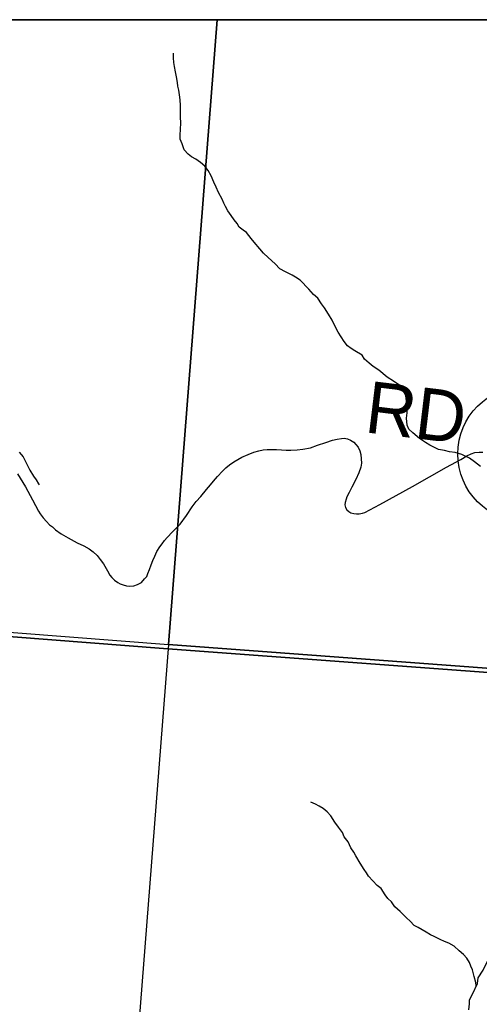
# Model space of a CAD drawing. Extents: x 0 to 82.7, y -0.2 to 22.
# Drawn here: x 7.785 to 8.291, y 19.817 to 20.9 of the extents above; entities that cross this region are included whole.
import ezdxf

# ---------------------------------------------------------------- set-up
doc = ezdxf.new("R2010")
doc.units = 0
for name, color, linetype in [('GM_X_County_Road', 7, 'Continuous'), ('GM_X_County_Road_Text', 7, 'Continuous'), ('GM_X_Minor_River', 7, 'Continuous'), ('GM_X_Section', 7, 'Continuous'), ('GM_X_Township_Text', 7, 'Continuous'), ('GM_X_Unincorporated', 7, 'Continuous'), ('SH_Cut_Line', 7, 'Continuous'), ('SH_Data', 7, 'Continuous')]:
    doc.layers.add(name, color=color, linetype=linetype)

msp = doc.modelspace()

# ---------------------------------------------------------------- linework, layer by layer
at = {"layer": 'GM_X_County_Road'}
for points in [[(8.0024, 20.9), (6.9771, 20.9), (6.9306, 20.2917), (7.9492, 20.2127)], [(8.9, 20.1421), (8.9, 20.9), (8.0024, 20.9), (7.9492, 20.2127)], [(8.9, 19.3224), (8.9, 20.1421), (7.9492, 20.2127), (7.8698, 19.2002), (8.8838, 19.1258)]]:
    msp.add_lwpolyline(points, close=True, dxfattribs=at)
msp.add_lwpolyline([(7.7829, 20.4005), (7.7918, 20.3861), (7.7995, 20.3718), (7.8062, 20.3594), (7.808, 20.3565), (7.8112, 20.3523), (7.8149, 20.3481), (7.8183, 20.3446), (7.8214, 20.3421), (7.8249, 20.3391), (7.831, 20.3346), (7.8387, 20.3302), (7.8484, 20.3247), (7.8558, 20.3212), (7.8618, 20.318), (7.866, 20.3149), (7.8706, 20.3107), (7.874, 20.3065), (7.8776, 20.3014), (7.8818, 20.2939), (7.8844, 20.2892), (7.8866, 20.2866), (7.8898, 20.2836), (7.8933, 20.2812), (7.8959, 20.2797), (7.8992, 20.2784), (7.9028, 20.2774), (7.9064, 20.2771), (7.9109, 20.2775), (7.9148, 20.2787), (7.9192, 20.2812), (7.9227, 20.2849), (7.9251, 20.2878), (7.9262, 20.2908), (7.928, 20.2952), (7.9301, 20.3004), (7.9319, 20.3051), (7.9339, 20.31), (7.9362, 20.3152), (7.9395, 20.3202), (7.9422, 20.3237), (7.9447, 20.3271), (7.9477, 20.3304), (7.9534, 20.3366), (7.9617, 20.3453), (7.969, 20.3547), (7.9752, 20.3644), (7.9795, 20.3701), (7.9845, 20.3757), (7.9908, 20.3832), (7.9954, 20.3885), (7.9985, 20.3924), (8.0029, 20.3978), (8.0083, 20.4033), (8.012, 20.4072), (8.0162, 20.4104), (8.021, 20.4139), (8.0298, 20.4189), (8.0365, 20.4217), (8.0429, 20.4244), (8.0485, 20.4259), (8.0531, 20.4268), (8.0574, 20.4273), (8.0635, 20.4273), (8.068, 20.4274), (8.0732, 20.427), (8.0785, 20.4267), (8.0837, 20.4266), (8.0904, 20.4269), (8.0969, 20.4277), (8.1053, 20.4293), (8.1131, 20.432), (8.1222, 20.4349), (8.1296, 20.4377), (8.1345, 20.4387), (8.1395, 20.4395), (8.1422, 20.4398), (8.1458, 20.439), (8.1493, 20.4374), (8.1529, 20.4352), (8.1552, 20.4329), (8.1576, 20.4299), (8.1595, 20.426), (8.1606, 20.4217), (8.1611, 20.417), (8.1612, 20.4123), (8.1607, 20.408), (8.1585, 20.4016), (8.1552, 20.3944), (8.1506, 20.3858), (8.1477, 20.3801), (8.1452, 20.3754), (8.1443, 20.3727), (8.1433, 20.3692), (8.1431, 20.3665), (8.1439, 20.3636), (8.1453, 20.361), (8.1474, 20.359), (8.1496, 20.3577), (8.1529, 20.3568), (8.1558, 20.3564), (8.1589, 20.3566), (8.1623, 20.3574), (8.1651, 20.3582), (8.1704, 20.3608), (8.1815, 20.3667), (8.2175, 20.3868), (8.2549, 20.4079), (8.2704, 20.4164), (8.2772, 20.4203), (8.282, 20.4225), (8.2859, 20.4239), (8.2907, 20.4244), (8.2947, 20.4244)], dxfattribs=at)
at = {"layer": 'GM_X_Minor_River'}
for points in [[(8.2921, 20.4085), (8.2857, 20.4139), (8.2801, 20.4178), (8.2718, 20.4217), (8.2642, 20.4241), (8.2581, 20.4249), (8.2525, 20.4261), (8.246, 20.4273), (8.2408, 20.4297), (8.2366, 20.432), (8.2317, 20.4351), (8.2253, 20.4394), (8.2178, 20.4456), (8.2133, 20.4498), (8.2114, 20.454), (8.2108, 20.4616), (8.2116, 20.4677), (8.2116, 20.4723), (8.2103, 20.4841), (8.2096, 20.4879), (8.2062, 20.494), (8.2036, 20.4978), (8.1964, 20.5025), (8.1897, 20.5067), (8.1803, 20.5145), (8.1742, 20.5187), (8.1697, 20.5222), (8.1645, 20.5268), (8.1619, 20.531), (8.154, 20.5357), (8.1498, 20.5384), (8.1461, 20.5415), (8.1423, 20.5461), (8.139, 20.5511), (8.1356, 20.5565), (8.1319, 20.5633), (8.1289, 20.5695), (8.1252, 20.5763), (8.1207, 20.5832), (8.1174, 20.5875), (8.1133, 20.5936), (8.1084, 20.5978), (8.1035, 20.6036), (8.0938, 20.6136), (8.0889, 20.6167), (8.0851, 20.619), (8.0776, 20.6226), (8.0715, 20.6261), (8.0663, 20.6314), (8.0588, 20.6384), (8.0535, 20.6434), (8.0494, 20.648), (8.0434, 20.6553), (8.0401, 20.6595), (8.0348, 20.666), (8.031, 20.6684), (8.0269, 20.6718), (8.0247, 20.6757), (8.0213, 20.6799), (8.018, 20.6845), (8.0142, 20.6899), (8.0116, 20.6945), (8.0098, 20.6983), (8.0079, 20.7025), (8.0042, 20.7098), (8.0016, 20.7159), (7.999, 20.7212), (7.9961, 20.7281), (7.9927, 20.7342), (7.989, 20.7388), (7.9841, 20.7431), (7.9792, 20.7466), (7.9743, 20.7493), (7.9706, 20.752), (7.9664, 20.757), (7.9639, 20.7635), (7.962, 20.7685), (7.9617, 20.773), (7.9621, 20.7795), (7.9626, 20.7863), (7.9623, 20.7932), (7.9624, 20.8057), (7.9618, 20.8118), (7.9611, 20.8175), (7.9604, 20.8224), (7.9593, 20.827), (7.9589, 20.8308), (7.9579, 20.8373), (7.9568, 20.8426), (7.9557, 20.8487), (7.955, 20.8529), (7.9547, 20.8579), (7.9544, 20.8632)], [(7.7847, 20.4245), (7.7892, 20.4191), (7.7921, 20.4133), (7.7966, 20.4045), (7.8007, 20.398), (7.8033, 20.3938), (7.8059, 20.3896), (7.8067, 20.3884)], [(8.2874, 19.8374), (8.2871, 19.8412), (8.2853, 19.8477), (8.2834, 19.8549), (8.2816, 19.8591), (8.2801, 19.8633), (8.2771, 19.8679), (8.2734, 19.8718), (8.2689, 19.876), (8.2633, 19.881), (8.2572, 19.8845), (8.2527, 19.8861), (8.2478, 19.8884), (8.2414, 19.8916), (8.2372, 19.8935), (8.2323, 19.8966), (8.2237, 19.9017), (8.2191, 19.904), (8.215, 19.9086), (8.2109, 19.9121), (8.2038, 19.9194), (8.1981, 19.9244), (8.1944, 19.9298), (8.1903, 19.9336), (8.1873, 19.9375), (8.1828, 19.9444), (8.1787, 19.9478), (8.1689, 19.9579), (8.1667, 19.9617), (8.1641, 19.9655), (8.16, 19.9724), (8.1551, 19.9804), (8.1529, 19.9843), (8.1496, 19.9893), (8.1466, 19.9958), (8.1421, 20.0015), (8.1406, 20.0061), (8.1362, 20.0118), (8.132, 20.0176), (8.1276, 20.0245), (8.1235, 20.0287), (8.1193, 20.0326), (8.1148, 20.0349), (8.1106, 20.0373), (8.1057, 20.0396)], [(8.2795, 19.8109), (8.28, 19.8177), (8.28, 19.8219), (8.2835, 19.8283), (8.289, 19.84), (8.2898, 19.8461), (8.2952, 19.8548), (8.3006, 19.8661), (8.3018, 19.871), (8.3076, 19.8805), (8.3092, 19.8846), (8.3138, 19.8925), (8.3162, 19.8963), (8.3196, 19.9005)]]:
    msp.add_lwpolyline(points, dxfattribs=at)
at = {"layer": 'GM_X_Section'}
msp.add_lwpolyline([(6.9306, 20.2917), (7.9492, 20.2127), (7.8698, 19.2002), (6.8524, 19.275)], close=True, dxfattribs=at)
at = {"layer": 'GM_X_Township_Text'}
msp.add_lwpolyline([(8.9, 20.1381), (8.9, 20.9), (6.1272, 20.9), (5.9756, 20.3782), (5.9672, 20.3493), (5.9906, 20.3478), (6.0773, 20.3422), (6.1569, 20.3371), (6.2809, 20.329), (6.7144, 20.301), (6.9227, 20.2875), (7.9434, 20.2083), (8.3897, 20.1756)], close=True, dxfattribs=at)
msp.add_lwpolyline([(8.9, 14.1), (8.9, 20.1381), (8.3897, 20.1756), (7.9434, 20.2083), (6.9227, 20.2875), (6.7144, 20.301), (6.2809, 20.329), (6.1569, 20.3371), (6.0773, 20.3422), (5.9906, 20.3478), (5.9672, 20.3493), (3.6288, 20.5056)], dxfattribs=at)
at = {"layer": 'GM_X_Unincorporated'}
msp.add_circle((8.3416, 20.4224), 0.0744, dxfattribs=at)
at = {"layer": 'SH_Cut_Line'}
msp.add_lwpolyline([(8.9, 14.1), (8.9, 20.9), (6.1272, 20.9), (5.9756, 20.3782), (5.9672, 20.3493), (3.6288, 20.5056), (3.179, 20.5374), (2.884, 20.5583), (2.8651, 20.279), (2.8645, 20.2703), (2.8645, 20.2693), (2.8288, 19.7415), (2.7788, 19.0007), (2.7784, 18.9951), (2.7199, 18.1299), (3.0279, 17.3486), (3.0556, 17.2782), (3.2909, 16.7562), (3.4071, 16.476), (3.6125, 15.9807), (3.8036, 15.5496), (4.1209, 14.8338)], dxfattribs=at)
at = {"layer": 'SH_Data'}
msp.add_line((2.1, 20.9), (8.9, 20.9), dxfattribs=at)

# ---------------------------------------------------------------- texts
at = {"layer": 'GM_X_County_Road_Text'}
msp.add_text('RD', height=0.05682, rotation=353.1174, dxfattribs=at).set_placement((8.1636, 20.4464))

doc.saveas('drawing.dxf')
